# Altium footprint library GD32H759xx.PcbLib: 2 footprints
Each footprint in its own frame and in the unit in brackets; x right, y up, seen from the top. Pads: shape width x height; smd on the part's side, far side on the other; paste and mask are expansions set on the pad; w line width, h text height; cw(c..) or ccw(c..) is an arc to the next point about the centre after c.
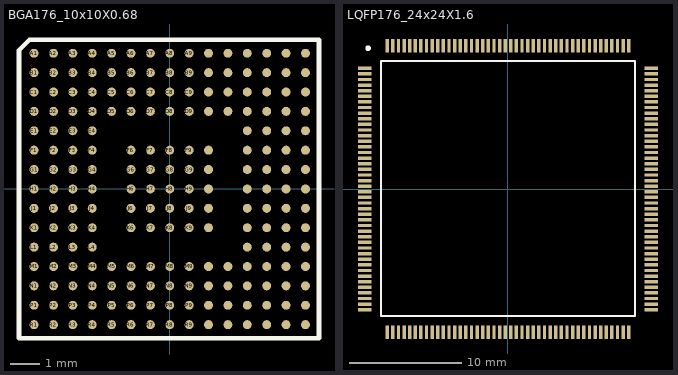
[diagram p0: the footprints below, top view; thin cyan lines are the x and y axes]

## BGA176_10x10X0.68 [mm]
pads (201):
  round 0.3 smd mask+0.05: A1(-4.55,4.55) A2(-3.9,4.55) A3(-3.25,4.55) A4(-2.6,4.55) A5(-1.95,4.55) A6(-1.3,4.55) A7(-0.65,4.55) A8(0,4.55) A9(0.65,4.55) A10(1.3,4.55) A11(1.95,4.55) A12(2.6,4.55) A13(3.25,4.55) A14(3.9,4.55) A15(4.55,4.55) B1(-4.55,3.9) B2(-3.9,3.9) B3(-3.25,3.9) B4(-2.6,3.9) B5(-1.95,3.9) B6(-1.3,3.9) B7(-0.65,3.9) B8(0,3.9) B9(0.65,3.9) B10(1.3,3.9) B11(1.95,3.9) B12(2.6,3.9) B13(3.25,3.9) B14(3.9,3.9) B15(4.55,3.9) C1(-4.55,3.25) C2(-3.9,3.25) C3(-3.25,3.25) C4(-2.6,3.25) C5(-1.95,3.25) C6(-1.3,3.25) C7(-0.65,3.25) C8(0,3.25) C9(0.65,3.25) C10(1.3,3.25) C11(1.95,3.25) C12(2.6,3.25) C13(3.25,3.25) C14(3.9,3.25) C15(4.55,3.25) D1(-4.55,2.6) D2(-3.9,2.6) D3(-3.25,2.6) D4(-2.6,2.6) D5(-1.95,2.6) D6(-1.3,2.6) D7(-0.65,2.6) D8(0,2.6) D9(0.65,2.6) D10(1.3,2.6) D11(1.95,2.6) D12(2.6,2.6) D13(3.25,2.6) D14(3.9,2.6) D15(4.55,2.6) E1(-4.55,1.95) E2(-3.9,1.95) E3(-3.25,1.95) E4(-2.6,1.95) E12(2.6,1.95) E13(3.25,1.95) E14(3.9,1.95) E15(4.55,1.95) F1(-4.55,1.3) F2(-3.9,1.3) F3(-3.25,1.3) F4(-2.6,1.3) F6(-1.3,1.3) F7(-0.65,1.3) F8(0,1.3) F9(0.65,1.3) F10(1.3,1.3) F12(2.6,1.3) F13(3.25,1.3) F14(3.9,1.3) F15(4.55,1.3) G1(-4.55,0.65) G2(-3.9,0.65) G3(-3.25,0.65) G4(-2.6,0.65) G6(-1.3,0.65) G7(-0.65,0.65) G8(0,0.65) G9(0.65,0.65) G10(1.3,0.65) G12(2.6,0.65) G13(3.25,0.65) G14(3.9,0.65) G15(4.55,0.65) H1(-4.55,0) H2(-3.9,0) H3(-3.25,0) H4(-2.6,0) H6(-1.3,0) H7(-0.65,0) H8(0,0) H9(0.65,0) H10(1.3,0) H12(2.6,0) H13(3.25,0) H14(3.9,0) H15(4.55,0) J1(-4.55,-0.65) J2(-3.9,-0.65) J3(-3.25,-0.65) J4(-2.6,-0.65) J6(-1.3,-0.65) J7(-0.65,-0.65) J8(0,-0.65) J9(0.65,-0.65) J10(1.3,-0.65) J12(2.6,-0.65) J13(3.25,-0.65) J14(3.9,-0.65) J15(4.55,-0.65) K1(-4.55,-1.3) K2(-3.9,-1.3) K3(-3.25,-1.3) K4(-2.6,-1.3) K6(-1.3,-1.3) K7(-0.65,-1.3) K8(0,-1.3) K9(0.65,-1.3) K10(1.3,-1.3) K12(2.6,-1.3) K13(3.25,-1.3) K14(3.9,-1.3) K15(4.55,-1.3) L1(-4.55,-1.95) L2(-3.9,-1.95) L3(-3.25,-1.95) L4(-2.6,-1.95) L12(2.6,-1.95) L13(3.25,-1.95) L14(3.9,-1.95) L15(4.55,-1.95) M1(-4.55,-2.6) M2(-3.9,-2.6) M3(-3.25,-2.6) M4(-2.6,-2.6) M5(-1.95,-2.6) M6(-1.3,-2.6) M7(-0.65,-2.6) M8(0,-2.6) M9(0.65,-2.6) M10(1.3,-2.6) M11(1.95,-2.6) M12(2.6,-2.6) M13(3.25,-2.6) M14(3.9,-2.6) M15(4.55,-2.6) N1(-4.55,-3.25) N2(-3.9,-3.25) N3(-3.25,-3.25) N4(-2.6,-3.25) N5(-1.95,-3.25) N6(-1.3,-3.25) N7(-0.65,-3.25) N8(0,-3.25) N9(0.65,-3.25) N10(1.3,-3.25) N11(1.95,-3.25) N12(2.6,-3.25) N13(3.25,-3.25) N14(3.9,-3.25) N15(4.55,-3.25) P1(-4.55,-3.9) P2(-3.9,-3.9) P3(-3.25,-3.9) P4(-2.6,-3.9) P5(-1.95,-3.9) P6(-1.3,-3.9) P7(-0.65,-3.9) P8(0,-3.9) P9(0.65,-3.9) P10(1.3,-3.9) P11(1.95,-3.9) P12(2.6,-3.9) P13(3.25,-3.9) P14(3.9,-3.9) P15(4.55,-3.9) R1(-4.55,-4.55) R2(-3.9,-4.55) R3(-3.25,-4.55) R4(-2.6,-4.55) R5(-1.95,-4.55) R6(-1.3,-4.55) R7(-0.65,-4.55) R8(0,-4.55) R9(0.65,-4.55) R10(1.3,-4.55) R11(1.95,-4.55) R12(2.6,-4.55) R13(3.25,-4.55) R14(3.9,-4.55) R15(4.55,-4.55)
Top Overlay:
  lines w0.152: -5.055,-5.004 5.004,-5.004 5.004,5 -4.703,5 -5.055,4.648 -5.055,-5.004
3D body "BGA176C65P15X15_1000X1000X68.step": height 0.68, standoff 0, extent -5,-5 5,5

## LQFP176_24x24X1.6 [mm]
pads (176):
  rect 1.2x0.3 smd: 1(-12.75,10.75) 2(-12.75,10.25) 3(-12.75,9.75) 4(-12.75,9.25) 5(-12.75,8.75) 6(-12.75,8.25) 7(-12.75,7.75) 8(-12.75,7.25) 9(-12.75,6.75) 10(-12.75,6.25) 11(-12.75,5.75) 12(-12.75,5.25) 13(-12.75,4.75) 14(-12.75,4.25) 15(-12.75,3.75) 16(-12.75,3.25) 17(-12.75,2.75) 18(-12.75,2.25) 19(-12.75,1.75) 20(-12.75,1.25) 21(-12.75,0.75) 22(-12.75,0.25) 23(-12.75,-0.25) 24(-12.75,-0.75) 25(-12.75,-1.25) 26(-12.75,-1.75) 27(-12.75,-2.25) 28(-12.75,-2.75) 29(-12.75,-3.25) 30(-12.75,-3.75) 31(-12.75,-4.25) 32(-12.75,-4.75) 33(-12.75,-5.25) 34(-12.75,-5.75) 35(-12.75,-6.25) 36(-12.75,-6.75) 37(-12.75,-7.25) 38(-12.75,-7.75) 39(-12.75,-8.25) 40(-12.75,-8.75) 41(-12.75,-9.25) 42(-12.75,-9.75) 43(-12.75,-10.25) 44(-12.75,-10.75) 89(12.75,-10.75) 90(12.75,-10.25) 91(12.75,-9.75) 92(12.75,-9.25) 93(12.75,-8.75) 94(12.75,-8.25) 95(12.75,-7.75) 96(12.75,-7.25) 97(12.75,-6.75) 98(12.75,-6.25) 99(12.75,-5.75) 100(12.75,-5.25) 101(12.75,-4.75) 102(12.75,-4.25) 103(12.75,-3.75) 104(12.75,-3.25) 105(12.75,-2.75) 106(12.75,-2.25) 107(12.75,-1.75) 108(12.75,-1.25) 109(12.75,-0.75) 110(12.75,-0.25) 111(12.75,0.25) 112(12.75,0.75) 113(12.75,1.25) 114(12.75,1.75) 115(12.75,2.25) 116(12.75,2.75) 117(12.75,3.25) 118(12.75,3.75) 119(12.75,4.25) 120(12.75,4.75) 121(12.75,5.25) 122(12.75,5.75) 123(12.75,6.25) 124(12.75,6.75) 125(12.75,7.25) 126(12.75,7.75) 127(12.75,8.25) 128(12.75,8.75) 129(12.75,9.25) 130(12.75,9.75) 131(12.75,10.25) 132(12.75,10.75)
  rect 0.3x1.2 smd: 45(-10.75,-12.75) 46(-10.25,-12.75) 47(-9.75,-12.75) 48(-9.25,-12.75) 49(-8.75,-12.75) 50(-8.25,-12.75) 51(-7.75,-12.75) 52(-7.25,-12.75) 53(-6.75,-12.75) 54(-6.25,-12.75) 55(-5.75,-12.75) 56(-5.25,-12.75) 57(-4.75,-12.75) 58(-4.25,-12.75) 59(-3.75,-12.75) 60(-3.25,-12.75) 61(-2.75,-12.75) 62(-2.25,-12.75) 63(-1.75,-12.75) 64(-1.25,-12.75) 65(-0.75,-12.75) 66(-0.25,-12.75) 67(0.25,-12.75) 68(0.75,-12.75) 69(1.25,-12.75) 70(1.75,-12.75) 71(2.25,-12.75) 72(2.75,-12.75) 73(3.25,-12.75) 74(3.75,-12.75) 75(4.25,-12.75) 76(4.75,-12.75) 77(5.25,-12.75) 78(5.75,-12.75) 79(6.25,-12.75) 80(6.75,-12.75) 81(7.25,-12.75) 82(7.75,-12.75) 83(8.25,-12.75) 84(8.75,-12.75) 85(9.25,-12.75) 86(9.75,-12.75) 87(10.25,-12.75) 88(10.75,-12.75) 133(10.75,12.75) 134(10.25,12.75) 135(9.75,12.75) 136(9.25,12.75) 137(8.75,12.75) 138(8.25,12.75) 139(7.75,12.75) 140(7.25,12.75) 141(6.75,12.75) 142(6.25,12.75) 143(5.75,12.75) 144(5.25,12.75) 145(4.75,12.75) 146(4.25,12.75) 147(3.75,12.75) 148(3.25,12.75) 149(2.75,12.75) 150(2.25,12.75) 151(1.75,12.75) 152(1.25,12.75) 153(0.75,12.75) 154(0.25,12.75) 155(-0.25,12.75) 156(-0.75,12.75) 157(-1.25,12.75) 158(-1.75,12.75) 159(-2.25,12.75) 160(-2.75,12.75) 161(-3.25,12.75) 162(-3.75,12.75) 163(-4.25,12.75) 164(-4.75,12.75) 165(-5.25,12.75) 166(-5.75,12.75) 167(-6.25,12.75) 168(-6.75,12.75) 169(-7.25,12.75) 170(-7.75,12.75) 171(-8.25,12.75) 172(-8.75,12.75) 173(-9.25,12.75) 174(-9.75,12.75) 175(-10.25,12.75) 176(-10.75,12.75)
Top Overlay:
  circle w0.254: c-12.446,12.528 r0.127
  lines w0.203: -11.303,-11.303 -11.303,11.385 11.303,11.385 11.303,-11.303 -11.303,-11.303
3D body "TSQFP50P2600X2600X160-176N.step": height 1.6, standoff 0, extent -13,-13 13,13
